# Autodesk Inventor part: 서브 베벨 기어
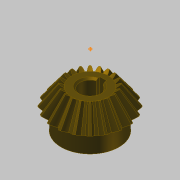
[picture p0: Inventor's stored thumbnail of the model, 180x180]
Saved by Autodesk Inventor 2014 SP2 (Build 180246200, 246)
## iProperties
Created: 2016-04
Part Number: 서브 베벨 기어
Material: 강철, 탄소
Document SubType Name: Modeling
Designer: mdu
Categories: <?xml version="1.0" encoding="UTF-16"?> <MemberInstance><Categories><FamilyTemplate><FamilyTemplateParameter ValueType="xs:double" Id="1" ObjectReferenceKey="da
Mass: 135.037 g
Surface Area: 63.6518 cm^2
Volume: 17.1585 cm^3
Density: 7.87 g/cm^3
Appearance: 얼룩무늬
CustomPartVersion: 1
Author: mdu
Revision Number: 1
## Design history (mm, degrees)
node "맨 위 점"
node "메쉬 평면2"
sketch "톱니 본체 스케치"
  geometry: L1 (0, 0)-(18.003, -31.331); L2 (18.003, -31.331)-(21.664, -28.891); L3 (21.664, -28.891)-(0, 0); L4 (20, -30)-(0, 0); L5 (10.813, -18.818)-(13.012, -17.352); L6 (18.003, -31.331)-(10.813, -18.818); L7 (21.664, -28.891)-(13.012, -17.352); L8 (0, -39.387)-(0, 6.564) reference; L9 (0, -30)-(21.664, -30)
  constraints: 16 end point, 4 point on line, 3 perpendicular, 2 collinear, 1 horizontal alignment, 1 vertical alignment
  dimensions: "d0" = 40 diameter of L4.start L8 (= da_de); "d1" = 36.00616 diameter of L1.end L8 (= da_dfe); "d2" = 43.3282 diameter of L2.end L8 (= da_dae); "d3" = 14.4 distance between parallel lines of L2 L5 (= da_b); "d4" = 28.8906 vertical distance of L2.end L1.start (= da_ve)
revolve "톱니 본체" sketch "톱니 본체 스케치" stored, may be unused: angle "d5" = 90 deg
node "시작점"
node "톱니 평면"
sketch "시작 스케치"
  geometry: L1 (0, -23.505)-(0, 10.645) reference; L2 (-0.834, -2.928)-(0.834, -2.928); A1 r 8.898 centre (-9.698, -3.713) between (-0.834, -2.928) and (-3.903, 3.04); A2 r 8.898 centre (9.698, -3.713) between (3.903, 3.04) and (0.834, -2.928); A3 r 27.357 centre (0, -24.037) between (3.903, 3.04) and (-3.903, 3.04); 1 further point
  constraints: 6 point on circle, 3 centre point, 3 symmetric about line, 2 end point, 1 coincident, 1 perpendicular, 1 other
  dimensions: "d7" = 8.89846 radius of A1 (= fd_rr); "d8" = 9.69794 horizontal distance of point (0, -24.037) A1.centre (= fd_x); "d9" = 20.32439 vertical distance of point (0, -24.037) A1.centre (= fd_y); "d57" = 27.35701 radius of A3 (= 0.5 x fd_dva + 0.3 x da_he); "d58" = 21.10901 distance from line of A3.centre L2 (= 0.5 x fd_dva - 1.12 x da_he)
node "끝점"
  node "끝 평면"
sketch "3D 스케치 오른쪽"
  node "Helical Curve Right" dims "d65" = 229.90621 (computed from da_dm, da_delta, da_beta), "d66" = 31.5, "d67" = 40 (= da_de), "d68" = -5.88003 (= -da_delta), "d69" = 12.16458 (computed from fd_loft, da_delta)
node "끝 평면 오른쪽"
sketch "끝 스케치 오른쪽"
  geometry: L1 (0, -22.649)-(0, 12.15) reference; L2 (-0.497, -1.72)-(0.497, -1.72); A1 r 5.299 centre (-5.775, -2.187) between (-0.497, -1.72) and (-2.324, 1.834); A2 r 5.299 centre (5.775, -2.187) between (2.324, 1.834) and (0.497, -1.72); A3 r 16.291 centre (0, -14.29) between (2.324, 1.834) and (-2.324, 1.834); 1 further point
  constraints: 6 point on circle, 3 centre point, 3 symmetric about line, 2 end point, 1 coincident, 1 perpendicular, 1 other
  dimensions: "d70" = 5.77526 horizontal distance of A3.centre A1.centre (computed from fd_x, fd_ratio); "d71" = 12.10346 vertical distance of point (0, -14.29) A1.centre (computed from fd_y, fd_ratio); "d72" = 5.29916 radius of A1 (computed from fd_rr, fd_ratio); "d73" = 12.57071 distance from line of point (0, -14.29) L2 (computed from d58, fd_ratio); "d74" = 16.29149 radius of A3 (computed from d57, fd_ratio)
feature "로프트 오른쪽" sketch "끝 스케치 오른쪽" dims "d75" = 0, "d77" = 0, "d79" = 0, "d80" = 90 deg, "d85" = 20, "d92" = 90 deg, "d93" = 90 deg, "da_teethtype" = 0 [user parameter]
sketch "3D 스케치 왼쪽"
  node "Helical Curve Left" dims "d26" = 229.90621 (computed from da_dm, da_delta, da_beta), "d27" = 12.16458 (computed from fd_loft, da_delta), "d28" = 40 (= da_de), "d29" = -5.88003 (= -da_delta)
node "끝 평면 왼쪽"
sketch "끝 스케치 왼쪽" dims "d56" = 10.82768 (derived)
  geometry: L1 (0, -35.087)-(0, 18.089) reference; L2 (-0.497, -1.716)-(0.497, -1.716); A1 r 5.299 centre (-5.775, -2.183) between (-0.497, -1.716) and (-2.324, 1.838); A2 r 5.299 centre (5.775, -2.183) between (2.324, 1.838) and (0.497, -1.716); A3 r 16.291 centre (0, -14.287) between (2.324, 1.838) and (-2.324, 1.838); 2 further points; 1 other entity
  constraints: 6 point on circle, 3 centre point, 3 symmetric about line, 2 end point, 1 coincident, 2 other
  dimensions: "d30" = 5.29916 radius of A1 (computed from fd_rr, fd_ratio); "d31" = 5.77526 horizontal distance of point (0, -14.287) A1.centre (computed from fd_x, fd_ratio); "d32" = 12.10346 vertical distance of A1.centre point (0, -14.287) (computed from fd_y, fd_ratio); "d61" = 16.29149 radius of A3 (computed from d57, fd_ratio); "d62" = 12.57071 distance from line of point (0, -14.287) L2 (computed from d58, fd_ratio)
feature "로프트 왼쪽" sketch "끝 스케치 왼쪽" dims "d35" = 0, "d37" = 0, "d39" = 0, "d40" = 90 deg, "d84" = 10, "d90" = 90 deg, "d91" = 90 deg, "da_teethtype" = 0 [user parameter]
sketch "본체 스케치"
  geometry: L1 (0, -35.038)-(0, -19.531) reference; L2 (18.003, -31.331)-(10.813, -18.818) reference; L3 (10.813, -18.818)-(0, -18.818); L4 (18.003, -31.331)-(0, -31.331)
  constraints: 4 end point, 2 perpendicular, 2 point on line
revolve "본체 고정" sketch "본체 스케치" stored, may be unused: angle "d46" = 90 deg
feature "피치 지름" dims angle "d47" = 90 deg
sketch "스케치8"
  geometry: C1 r 17 at (0, 0); 1 further point
  constraints: 1 centre point, 1 coincident
  dimensions: "d94" = 34 diameter of C1
extrude "돌출1" join sketch "스케치8" distance "d95" = 10; taper "d96" = 0 deg
sketch "스케치9"
  geometry: 1 further point
hole "구멍1" sketch "스케치9" at (0, 0) diameter "d97" = 12; stored, may be unused: countersink angle "d101" = 90 deg, drill point angle "d103" = 118 deg; dims "d98" = 6, "d99" = 4, "d100" = 2, "d102" = 8
sketch "스케치10"
  geometry: 1 further point
sketch "스케치11"
  geometry: 1 further point
sketch "스케치12"
  geometry: L1 (-2, 5.657)-(-2, 7.8); L2 (-2, 7.8)-(2, 7.8); L3 (2, 7.8)-(2, 5.657); A1 r 6 centre (0, 0) between (-2, 5.657) and (2, 5.657) reference; 1 further point
  constraints: 6 end point, 2 parallel, 2 point on circle, 1 perpendicular, 1 vertical
  dimensions: "d104" = 4 distance of L1.end L2.end; "d105" = 13.8 dimension on A1 L2
extrude "돌출2" cut sketch "스케치12" stored distance "d106" = 7; taper "d107" = 0 deg
chamfer "모따기1" distance "d108" = 1; stored, may be unused: second distance "d109" = 2, angle "d110" = 45 deg
body "Solid1"
feature "로프트" dims "d17" = 0, "d18" = 90 deg, "d19" = 0, "d20" = 90 deg, "d89" = 0, "da_teethtype" = 0 [user parameter]
pattern_circular "원형 패턴" dims angle "d22" = 360 deg, "d88" = 0, "da_teethtype" = 0 [user parameter]
pattern_circular "원형 패턴 오른쪽" dims angle "d82" = 360 deg, "da_teethtype" = 0 [user parameter]
pattern_circular "원형 패턴 왼쪽" dims angle "d42" = 360 deg, "da_teethtype" = 0 [user parameter]
sketch "끝 스케치"
  geometry: L1 (0, -15.359)-(0, 6.983) reference; L2 (-0.497, -1.72)-(0.497, -1.72); A1 r 5.299 centre (-5.775, -2.187) between (-0.497, -1.72) and (-2.324, 1.834); A2 r 5.299 centre (5.775, -2.187) between (2.324, 1.834) and (0.497, -1.72); A3 r 16.291 centre (0, -14.29) between (2.324, 1.834) and (-2.324, 1.834); 1 further point
  constraints: 6 point on circle, 3 centre point, 3 symmetric about line, 2 end point, 1 coincident, 1 other
  dimensions: "d12" = 5.29916 radius of A1 (computed from fd_rr, fd_ratio); "d15" = 5.77526 horizontal distance of A1.centre point (0, -14.29) (computed from fd_x, fd_ratio); "d16" = 12.10346 vertical distance of A1.centre point (0, -14.29) (computed from fd_y, fd_ratio); "d59" = 16.29149 radius of A3 (computed from d57, fd_ratio); "d60" = 12.57071 distance from line of A3.centre L2 (computed from d58, fd_ratio)
sketch "Sketch6"
  geometry: L1 (20, -30)-(0, 0) reference; L2 (0, -37.8)-(0, 6.3) reference
body "Srf1"
other parameters: "da_b" = 14.4 [user parameter; used in 2 equation terms], "da_de" = 40 [user parameter; used in 4 equation terms], "da_dae" = 43.3282 [user parameter; used in 2 equation terms], "da_dfe" = 36.00616 [user parameter; used in 1 equation term], "da_le" = 36.05551 [user parameter; used in 1 equation term], "da_omega" = 90 deg [user parameter; used in 1 equation term], "da_beta" = 0 [user parameter; used in 2 equation terms], "da_delta" = 5.88003 [user parameter; used in 8 equation terms], "da_alpha" = 20 deg [user parameter; used in 2 equation terms], "da_he" = 4.4 [user parameter; used in 4 equation terms], "da_ve" = 28.8906 [user parameter; used in 1 equation term], "fd_dv" = 48.07402 (computed from da_de, da_delta) [user parameter; used in 1 equation term], "fd_dva" = 52.07402 (computed from da_dae, da_delta) [user parameter; used in 3 equation terms], "fd_dvb" = 45.1748 (computed from fd_dv, da_alpha) [user parameter; used in 2 equation terms], "da_zv" = 240.37008 [user parameter; used in 1 equation term], "fd_loft" = 14.62 (= da_b + 0.05 x da_he) [user parameter; used in 4 equation terms], "fd_ratio" = 5.95514 (computed from da_le, fd_loft) [user parameter; used in 15 equation terms], "fd_rr" = 8.89846 (computed from fd_dd, fd_dvb) [user parameter; used in 6 equation terms], "fd_angle" = 0.66075 (computed from da_zv) [user parameter; used in 4 equation terms], "fd_x1" = 1.58709 (computed from da_dvw, fd_angle) [user parameter; used in 1 equation term], "fd_y1" = 23.98456 (computed from da_dvw, fd_angle) [user parameter; used in 1 equation term], "fd_x2" = 8.11084 (computed from fd_rr, fd_angle2, fd_angle) [user parameter; used in 1 equation term], "fd_y2" = 3.66016 (computed from fd_rr, fd_angle2, fd_angle) [user parameter; used in 1 equation term], "fd_x" = 9.69794 (= fd_x1 + fd_x2) [user parameter; used in 4 equation terms], "fd_y" = 20.32439 (= fd_y1 - fd_y2) [user parameter; used in 4 equation terms], "fd_angle2" = 3.57832 (computed from fd_dvb, fd_dd, da_alpha) [user parameter; used in 2 equation terms], "fd_dd" = 48.55402 (= fd_dva - 0.8 x da_he) [user parameter; used in 2 equation terms], "da_dvw" = 48.07402 [user parameter; used in 2 equation terms], "d11" = 14.62 (= fd_loft), "da_dm" = 32.01232 [user parameter; used in 2 equation terms], "da_x" = 0 [user parameter], "da_m" = 2 [user parameter], "d48" = 0, "d49" = 0, "d50" = 90 deg (= da_omega), "d51" = 9 deg (computed from da_z), "d52" = 0, "d53" = 0, "d54" = 0
